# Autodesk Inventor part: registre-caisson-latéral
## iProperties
Author: chr
Shininess: 21.0
PropertySet Name: _Private Model Information
Length Units: 11269
Angle Units: 11286
Time Units: 11279
Mass Units: 11290
Length Display Precision: 3
Angle Display Precision: 2
Compacted: False
Created: 2001-06
Part Number: registre-caisson-latéral
Material: Par défaut
Document SubType Name: Tôlerie
Designer: chr
Control State: 0
Master: False
Checked Out: False
PropertySet Name: Design Tracking Control
Density: 0.0
Volumn: 0.0
Area: 0.0
PropertySet Name: Model Information
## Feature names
1. Perçage1 [Hole]
2. Réseau rectangulaire1 [Rectangular Pattern]
3. Perçage2 [Hole]
4. Réseau rectangulaire2 [Rectangular Pattern]
5. Perçage3 [Hole]
6. Réseau rectangulaire3 [Rectangular Pattern]
7. Perçage4 [Hole]
8. Réseau rectangulaire4 [Rectangular Pattern]
9. Plaque1
10. Plaque2
11. Pli1
12. Plaque3
13. Pli2
14. Plaque4
15. Pli3
16. Plaque5
17. Pli4
